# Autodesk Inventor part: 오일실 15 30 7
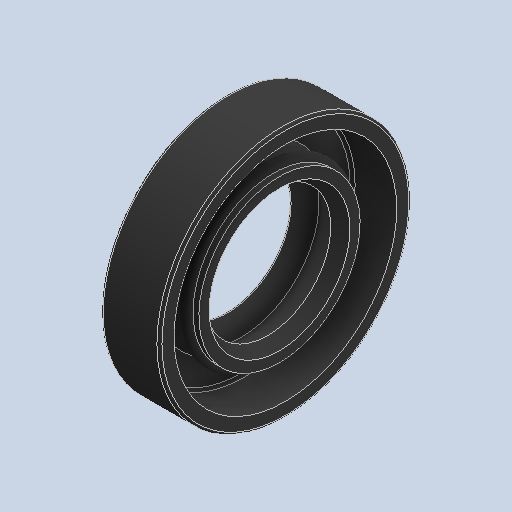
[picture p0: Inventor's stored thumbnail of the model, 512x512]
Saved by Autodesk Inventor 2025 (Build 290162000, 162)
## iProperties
Created: 2025-08
Part Number: 오일실 15 30 7
Material: 고무
Description: 오일-실
Document SubType Name: Modeling
Designer: infra02
Density: 0.93 g/cm^3
Appearance: 기본값
Author: jhkim
Sending System: Autodesk Inventor 2026
Preprocessor: ST-DEVELOPER v20.1
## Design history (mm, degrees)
feature "Solid1"
node "솔리드1"
